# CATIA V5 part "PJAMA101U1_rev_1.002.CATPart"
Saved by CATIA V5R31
Part number: JAMA101U1
Revision: 1
Nomenclature: SEAT_ANC
Source: Unknown
Property "部品番号(A社)": "JAMA101U1"
Property "部品名称(A社)": "SEAT_ANC"
Property "Version(A社)": "1"
Property "材質(A社)": "SS400B"
Bounding box of the stored display mesh (mm): x 4086.42 to 4141.807, y 476.307 to 534.757, z 624.356 to 661.826
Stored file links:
  \\solize.local\damia\dept\DDE_Design\10_order\2305701_JAMA_変換検証STEP3_お手本モデル作成\work\02_マツダ_板金\10_CATIA_V5\231211\PJAMA101U1_rev_1.002.CATPart
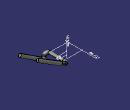
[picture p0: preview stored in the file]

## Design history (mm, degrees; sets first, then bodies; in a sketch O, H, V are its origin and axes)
TTRSSet1
f4a2d38f3ddc11d3a929006094b99c4b_11 "CATTPSSet"
Set1
  Plane1: type OffsetPt, RefPlane zx-plane, RefPoint vertex [face of Solid1 | face of Solid1 | face of Solid1]
  Plane2: type Offset, RefPlane Plane1, Offset 10, reversed
  Circle1: stored without definition
Body1 "MANIFOLD_SOLID_BREP #9746" (main body)
  Solid1: solid without history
